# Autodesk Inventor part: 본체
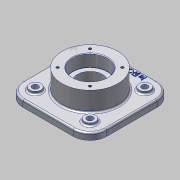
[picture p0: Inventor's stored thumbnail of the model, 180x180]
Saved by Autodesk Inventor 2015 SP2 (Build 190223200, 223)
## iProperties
Created: 2015-07
Part Number: 본체
Material: 알루미늄 6061
Document SubType Name: Modeling
Designer: AMC
Density: 2.7 g/cm^3
Appearance: 알루미늄 - 평지
Mass: 1458.87 g
Surface Area: 802.047 cm^2
Volume: 540.321 cm^3
Author: AMC
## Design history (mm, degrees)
sketch "스케치1"
  geometry: L1 (-75, 75)-(75, 75); L2 (75, 75)-(75, -75); L3 (75, -75)-(-75, -75); L4 (-75, -75)-(-75, 75); L5 (-75, 75)-(75, -75); L6 (75, 75)-(-75, -75); 1 further point
  constraints: 12 end point, 2 midpoint, 2 parallel, 1 horizontal, 1 perpendicular
  dimensions: "d0" = 150 distance of L2.end L3.end; "d1" = 150 distance of L1.end L2.end
extrude "돌출1" new body sketch "스케치1" distance "d2" = 12; taper "d3" = 0 deg
sketch "스케치2"
  geometry: L1 (-49, 49)-(49, -49); L2 (49, 49)-(-49, -49); C1 r 10 at (-49, 49); C2 r 10 at (49, 49); C3 r 10 at (49, -49); C4 r 10 at (-49, -49); 1 further point
  constraints: 4 centre point, 4 coincident, 4 end point, 2 midpoint
  dimensions: "d4" = 98 distance of L1.end L2.end; "d5" = 98 distance of L2.start L1.end; "d6" = 20 diameter of C1; "d7" = 20 diameter of C2; "d8" = 20 diameter of C3; "d9" = 20 diameter of C4
extrude "돌출2" join sketch "스케치2" distance "d11" = 5; taper "d12" = 0 deg
sketch "스케치3"
  geometry: C1 r 50 at (0, 0); 1 further point
  constraints: 1 centre point, 1 coincident
  dimensions: "d13" = 100 diameter of C1
extrude "돌출3" join sketch "스케치3" distance "d14" = 35; taper "d15" = 0 deg
sketch "스케치4"
  geometry: C1 r 50 at (0, 0); 1 further point
  constraints: 1 centre point, 1 coincident
  dimensions: "d16" = 100 diameter of C1
extrude "돌출4" join sketch "스케치4" distance "d17" = 23; taper "d18" = 0 deg
hole "구멍1" diameter "d21" = 11; stored, may be unused: countersink angle "d25" = 90 deg, drill point angle "d27" = 118 deg; dims "d19" = 10, "d20" = 10, "d22" = 6, "d23" = 4, "d24" = 2, "d26" = 8
hole "구멍2" diameter "d30" = 11; stored, may be unused: countersink angle "d34" = 90 deg, drill point angle "d36" = 118 deg; dims "d28" = 10, "d29" = 10, "d31" = 6, "d32" = 4, "d33" = 2, "d35" = 8
hole "구멍3" diameter "d39" = 11; stored, may be unused: countersink angle "d43" = 90 deg, drill point angle "d45" = 118 deg; dims "d37" = 10, "d38" = 10, "d40" = 6, "d41" = 4, "d42" = 2, "d44" = 8
hole "구멍4" diameter "d48" = 11; stored, may be unused: countersink angle "d52" = 90 deg, drill point angle "d54" = 118 deg; dims "d46" = 10, "d47" = 10, "d49" = 6, "d50" = 4, "d51" = 2, "d53" = 8
hole "구멍5" diameter "d57" = 45; stored, may be unused: countersink angle "d61" = 90 deg, drill point angle "d63" = 118 deg; dims "d55" = 10, "d56" = 10, "d58" = 6, "d59" = 62, "d60" = 22, "d62" = 50
hole "구멍6" diameter "d66" = 45; stored, may be unused: countersink angle "d70" = 90 deg, drill point angle "d72" = 0 deg; dims "d64" = 10, "d65" = 10, "d67" = 6, "d68" = 62, "d69" = 22, "d71" = 50
sketch "스케치5"
  geometry: 2 further points
hole "구멍7" sketch "스케치5" at (28.991, 28.991) diameter "d75" = 4.917; stored, may be unused: countersink angle "d79" = 90 deg, drill point angle "d81" = 118 deg; dims "d76" = 10, "d77" = 62, "d78" = 22, "d80" = 15.1
sketch "스케치6"
  geometry: 2 further points
hole "구멍8" sketch "스케치6" at (28.991, 28.991) diameter "d84" = 4.917; stored, may be unused: countersink angle "d88" = 90 deg, drill point angle "d90" = 118 deg; dims "d85" = 10, "d86" = 62, "d87" = 22, "d89" = 13
chamfer "모따기1" distance "d97" = 0.3; stored, may be unused: second distance "d98" = 2, angle "d99" = 45 deg
chamfer "모따기2" distance "d100" = 0.3; stored, may be unused: second distance "d101" = 2, angle "d102" = 45 deg
sketch "스케치7"
  geometry: 2 further points
  constraints: 1 other
feature "엠보싱1" sketch "스케치7" dims "d0" = 150, "d1" = 150, "d104" = 1, "d105" = 0
chamfer "모따기3" distance "d106" = 1; stored, may be unused: second distance "d107" = 2, angle "d108" = 45 deg
chamfer "모따기4" distance "d109" = 1; stored, may be unused: second distance "d110" = 2, angle "d111" = 45 deg
fillet "모깎기1" dims "d112" = 30
fillet "모깎기2" dims "d113" = 3
node "솔리드1"
pattern_circular "원형 패턴1" dims angle "d92" = 360 deg
pattern_circular "원형 패턴2" dims angle "d95" = 360 deg
